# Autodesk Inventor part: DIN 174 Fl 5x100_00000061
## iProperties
Created: 2006-03
Part Number: DIN 174 Fl 5x100_00000061
Material: Default
Document SubType Name: Modeling
Designer: Carlo
Stock Number: DIN 174 Fl 5x100
Mass: 773.849 g
Surface Area: 3260.58 cm^2
Volume: 773.849 cm^3
Density: 1 g/cm^3
G_L: 1547.896 mm
G_W: 5.000 mm
G_H: 100.000 mm
AFG_Item: 100 x 5
CSToolsMass: 1.0
CSToolsVolume: 773849.0
CSToolsArea: 3261.0
Author: Carlo
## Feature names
1. AFG_Detailed_DIN 174 Fl 5x100_00000061 [Extrusion]
2. AFG_Simplified_DIN 174 Fl 5x100_00000061 [Extrusion]
3. AFG_StartExtrusion_1 [Extrusion]
4. AFG_StartExtrusion_2 [Extrusion]
5. AFG_EndExtrusion_1 [Extrusion]
6. AFG_EndExtrusion_2 [Extrusion]
